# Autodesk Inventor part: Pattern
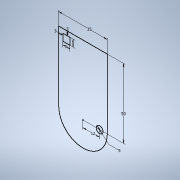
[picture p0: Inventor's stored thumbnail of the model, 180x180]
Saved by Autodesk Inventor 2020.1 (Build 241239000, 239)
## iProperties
Created: 2019-09
Part Number: Pattern
Material: Generic
Document SubType Name: Modeling
Designer: Synergysoft Dell02
Density: 1 g/cm^3
Appearance: Default
Author: Synergysoft Dell02
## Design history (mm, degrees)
sketch "Sketch1"
  geometry: L1 (-17.5, 0)-(-17.5, 50); L2 (-17.5, 50)-(17.5, 50); L3 (17.5, 50)-(17.5, 0); L4 (-14.5, 47)-(-9.5, 47); L5 (-9.5, 47)-(-9.5, 42); L6 (-9.5, 42)-(-14.5, 42); L7 (-14.5, 42)-(-14.5, 47); C1 r 2.5 at (12, 0); A1 r 17.5 centre (0, 0) between (-17.5, 0) and (17.5, 0); 1 further point
  constraints: 14 end point, 3 perpendicular, 2 centre point, 2 parallel, 2 point on circle, 2 tangent, 1 coincident, 1 horizontal, 1 horizontal alignment, 1 vertical
  dimensions: "d0" = 35 distance of L1.end L2.end; "d1" = 50 distance from line of A1.centre L2; "d2" = 5 distance of L5.end L6.end; "d3" = 5 distance of L4.end L5.end; "d4" = 3 distance between parallel lines of L2 L4; "d5" = 3 distance between parallel lines of L1 L7; "d6" = 5 diameter of C1; "d7" = 12 distance of C1.centre point (0, 0)
